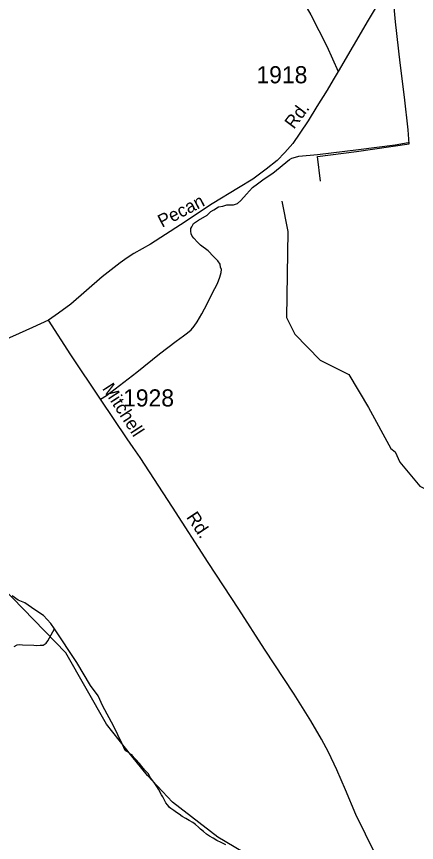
# Model space of a CAD drawing. Extents: x 2260773 to 2342389, y 552869 to 618546.
# Drawn here: x 2297558 to 2300476, y 569967 to 575994 of the extents above; entities that cross this region are included whole.
import ezdxf

# ---------------------------------------------------------------- set-up
doc = ezdxf.new("R2010")
doc.units = 0
for name, color, linetype in [('Exist Hydrographic Creek Single Shore', 7, 'Continuous'), ('Exist Hydrographic Misc Water Feature', 7, 'Continuous'), ('Exist Road Non-System Type 51', 7, 'Continuous'), ('Exist Road Secondary Type 51 Attributed', 7, 'Continuous'), ('Exist Road Secondary Type 51 Label', 7, 'Continuous'), ('Exist Road Secondary Type 51 Number Label', 7, 'Continuous')]:
    doc.layers.add(name, color=color, linetype=linetype)

msp = doc.modelspace()

# ---------------------------------------------------------------- linework, layer by layer
at = {"layer": 'Exist Hydrographic Creek Single Shore'}
for points in [[(2298399.1, 570596.1), (2298213.1, 570829.4), (2297917, 571350.3), (2297059.1, 572233.4), (2296418, 573084.2), (2296190, 573398.7), (2295828.9, 573770.1), (2295624.9, 574203.8), (2295539, 574477.8), (2295494.9, 574701.6), (2295534.9, 574851.6), (2295857.9, 575114.1), (2295931.9, 575247), (2295937, 575505.9), (2295807, 576118.6), (2295793.9, 576561.6), (2295972.9, 577053.2)], [(2299494, 574647), (2299537.9, 574425.6), (2299528.1, 573798.5), (2299586.9, 573676.2), (2299773.1, 573486.8), (2299982.1, 573380.4), (2300126, 573140.1), (2300288, 572841.5), (2300321, 572816.5), (2300355.1, 572742.5), (2300499, 572567.8), (2300607.1, 572513.1), (2300782, 572595.6), (2301451.1, 573052.5), (2302291.2, 573139), (2302582.1, 573232.7), (2303377.1, 573625.8), (2303791.1, 573885.4), (2304005.2, 574081.1), (2304087, 574205.8), (2304149.1, 574625.1), (2304155.1, 574914)], [(2299885.1, 566075.2), (2299874, 566373.4), (2299829.1, 566673.5), (2299719, 566895.4), (2299525, 567120.6), (2299474, 567226.9), (2299439.1, 567376.4), (2299412, 567503.3), (2299343.1, 567733.5), (2299367.1, 567875.5), (2299432.1, 567976.6), (2299478.1, 568309.9), (2299527.1, 568459.5), (2299517, 568593.7), (2299466, 568703.2), (2299456.9, 569510.1), (2299414.1, 569665.8), (2299346, 569764.8), (2299211.1, 569897.2), (2299026.9, 570004.7), (2298696.6, 570260.6), (2298514.3, 570455.8), (2298399.1, 570596.1)]]:
    msp.add_lwpolyline(points, dxfattribs=at)
at = {"layer": 'Exist Hydrographic Misc Water Feature'}
for points in [[(2299776.4, 574792.9), (2299752.8, 574972.5), (2300038.1, 575009.4), (2300423.3, 575063.7), (2300414.3, 575167.7), (2300387.5, 575405.3), (2300357.1, 575656.5), (2300323.7, 575953.8), (2300312.8, 576061.7), (2300295, 576197.8), (2300292.9, 576215.6), (2300284.3, 576243.6), (2300243.7, 576358.9), (2300202.1, 576472.6), (2300162.7, 576596.1), (2300142, 576669.8), (2300115.2, 576749.2), (2300092.6, 576815.1), (2300072.3, 576846.9)], [(2297833.9, 571526.5), (2297807.5, 571564.2), (2297755.2, 571622), (2297719.1, 571645.3), (2297666.6, 571682.7), (2297618.2, 571714.4), (2297570, 571735.8), (2297526, 571767.6)], [(2297541.5, 571395.8), (2297561.4, 571407.9), (2297579.1, 571412.1), (2297601.2, 571410.3), (2297683.2, 571407.4), (2297705, 571405.3), (2297731, 571405.8), (2297751.3, 571407.6), (2297774.9, 571421.9), (2297784.9, 571438.3), (2297833.9, 571526.5)], [(2298398.2, 570608.3), (2298394.6, 570606.4), (2298378.2, 570620.2), (2298362.2, 570631.5), (2298349.9, 570637.4), (2298327.7, 570687.8), (2298264.8, 570817.7), (2298187.3, 570962), (2298154.4, 571035.9), (2298097.6, 571111.4), (2297998.2, 571280), (2297833.9, 571526.5)], [(2299085.2, 569950.1), (2299050.7, 569967.8), (2299018.5, 569981.6), (2298992.7, 569997.3), (2298966.4, 570013), (2298944.3, 570028.4), (2298921.7, 570046.4), (2298900, 570063.9), (2298885.7, 570079.9), (2298863.7, 570097.8), (2298843.2, 570113.4), (2298817.2, 570127.1), (2298793, 570140.9), (2298766.7, 570156.6), (2298744.6, 570174.5), (2298724.9, 570186), (2298706.4, 570200.1), (2298682.2, 570213.9), (2298674.2, 570221.6), (2298668.3, 570229.4), (2298658.5, 570241.4), (2298648, 570255.2), (2298639.6, 570271.4), (2298631.8, 570285.2), (2298625.4, 570299.1), (2298615, 570314.9), (2298593, 570356.7), (2298580.7, 570374.4), (2298566.6, 570396.4), (2298552.2, 570418), (2298535.8, 570439.9), (2298518, 570469.8), (2298509.8, 570477.5), (2298503.4, 570485.3), (2298493.8, 570495.3), (2298483.3, 570507.4), (2298469.4, 570525), (2298457.1, 570541), (2298453, 570544.9), (2298431.1, 570570.9), (2298420.8, 570580.5), (2298404.6, 570600.4), (2298398.2, 570608.3)]]:
    msp.add_lwpolyline(points, dxfattribs=at)
at = {"layer": 'Exist Road Non-System Type 51'}
for points in [[(2298764.1, 576569.7), (2298834.8, 576661.3), (2298868.6, 576699.9), (2298905.5, 576730.4), (2298923.2, 576735.3), (2298963.9, 576735.1), (2299022.8, 576725.6), (2299156.2, 576703.1), (2299244.6, 576679.8), (2299288, 576657.3), (2299305.7, 576644.4), (2299324.9, 576621.9), (2299345.8, 576586.5), (2299402.1, 576499.7), (2299524.2, 576306.8), (2299609.4, 576170.9), (2299704.2, 576005.3), (2299821.5, 575777), (2299903.4, 575591.3)], [(2298170.1, 573201.6), (2298214.5, 573228.6), (2298309.3, 573300.9), (2298436.3, 573399), (2298600.2, 573532.5), (2298722.3, 573625.7), (2298775.4, 573664.3), (2298804.3, 573686), (2298831.6, 573708.5), (2298852.5, 573734.2), (2298875, 573766.4), (2298908.7, 573824.3), (2298948.9, 573898.2), (2298985.9, 573972.2), (2299022.8, 574046.2), (2299040.5, 574092.8), (2299050.2, 574124.9), (2299051.8, 574147.4), (2299046.9, 574165.1), (2299042.1, 574186), (2299026, 574211.8), (2298995.5, 574242.3), (2298956.9, 574284.1), (2298900.7, 574325.9), (2298878.2, 574346.8), (2298850.9, 574376.6), (2298839.6, 574391), (2298831.6, 574408.7), (2298830, 574426.4), (2298830, 574447.3), (2298836.4, 574460.2), (2298849.3, 574482.7), (2298884.6, 574506.8), (2298947.3, 574543), (2298976.2, 574570.3), (2298997.1, 574583.2), (2299030.9, 574604.1), (2299063, 574610.5), (2299091.9, 574618.5), (2299117.6, 574618.5), (2299141.7, 574618.5), (2299169.1, 574628.2), (2299194.8, 574650.7), (2299236.6, 574697.3), (2299279.9, 574745.6), (2299315.3, 574772.9), (2299363.5, 574808.3), (2299427.8, 574851.7), (2299548.3, 574949.8), (2299566, 574959.4), (2299593.3, 574967.4), (2299617.4, 574974.7), (2299754, 574985.9), (2300052.9, 575022.9), (2300319.6, 575058.3), (2300414.5, 575073.6)]]:
    msp.add_lwpolyline(points, dxfattribs=at)
at = {"layer": 'Exist Road Secondary Type 51 Attributed'}
for points in [[(2300459.9, 576531), (2300122, 575967.5), (2299903.4, 575591.3), (2299868.1, 575531.8), (2299823.1, 575455.4), (2299749.2, 575336.4), (2299684.9, 575231.9), (2299624.7, 575143), (2299572.4, 575067.9), (2299514.6, 575000.4), (2299458.3, 574944.1), (2299379.7, 574878.7), (2299281.6, 574807.5), (2299177.1, 574743.2), (2298985.9, 574625.8), (2298754.5, 574473), (2298534.3, 574331.5), (2298412.2, 574264), (2298365.6, 574231.9), (2298312.6, 574195.7), (2298182.4, 574093.6), (2297952.7, 573895.2), (2297864.7, 573828.6), (2297791, 573779.2)], [(2297791, 573779.2), (2297673, 573724.1), (2297406.8, 573605.3), (2296976.8, 573422.7), (2296796.5, 573349.7), (2296707.8, 573302.5), (2296601.9, 573233.7), (2296530.3, 573177.9), (2296448.7, 573107.7), (2296402.2, 573060)], [(2300174, 569885.1), (2300033.6, 570170.5), (2299956.5, 570350.5), (2299893.8, 570496.9), (2299834.3, 570627.1), (2299782.9, 570720.3), (2299704.2, 570855.4), (2299582.1, 571049.9), (2299366.7, 571377.9), (2299180.4, 571670.2), (2298954.8, 572009.5), (2298695, 572413.4), (2298458.8, 572775.2), (2298408.2, 572849.5), (2298364.3, 572911.8), (2298170.1, 573201.6), (2297953.4, 573525.1), (2297791, 573779.2)]]:
    msp.add_lwpolyline(points, dxfattribs=at)

# ---------------------------------------------------------------- texts
at = {"layer": 'Exist Road Secondary Type 51 Label'}
for s, rotation, p in [('Rd.', 52.93529, (2299581, 575166.9)), ('Pecan', 27.3629, (2298618.9, 574451.2)), ('Mitchell', 303.0048, (2298179.9, 573279.8)), ('Rd.', 303.66466, (2298793.2, 572340.9))]:
    msp.add_text(s, height=95, rotation=rotation, dxfattribs=at).set_placement(p)
at = {"layer": 'Exist Road Secondary Type 51 Number Label'}
for s, p in [('1918', (2299307.9, 575506.3)), ('1928', (2298334.9, 573148.2))]:
    msp.add_text(s, height=125, dxfattribs=at).set_placement(p)

doc.saveas('drawing.dxf')
